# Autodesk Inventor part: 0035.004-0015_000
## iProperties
Shininess: 20.0
Length Units: 11269
Angle Units: 11279
Time Units: 11290
Mass Units: 11283
Length Display Precision: 3
Angle Display Precision: 2
Created: 2003-10
Part Number: 0035.004-0015_000
Material: 1.4301 h6  X5CrNi18-10
Document SubType Name: Modellieren
Designer: Heimburger
Density: 0.0
Volumn: 0.0
Area: 0.0
PropertySet Name: Model Information
Control State: 0
Master: False
Checked Out: False
AIMD_ORIGIN: 0035.004-0011_000
Author: Heimburger
Title: Umlenkwelle
Subject: RD  ø20h6
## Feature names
1. Drehung1 [Revolution]
2. Fase1 [Chamfer]
